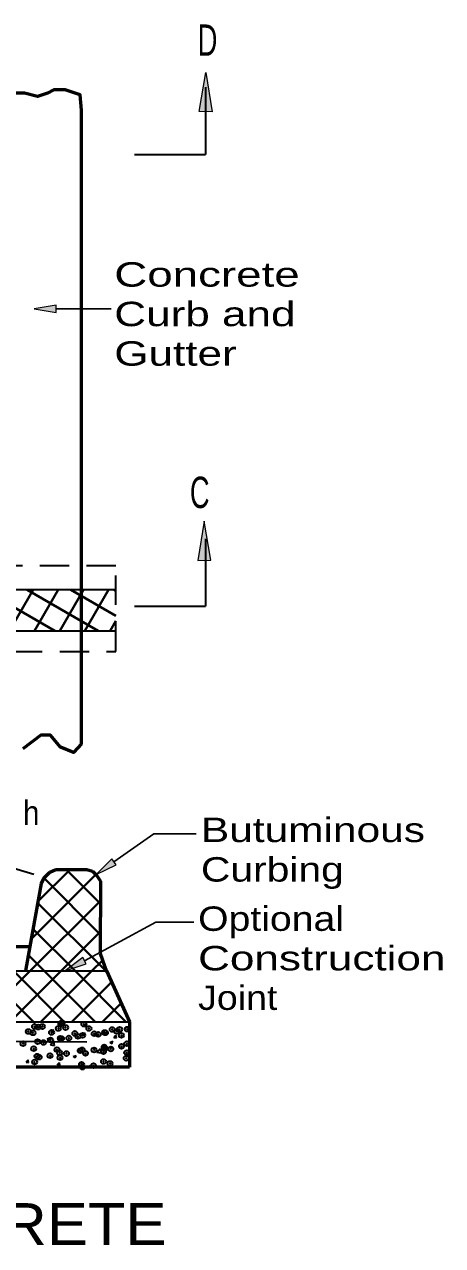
# Model space of a CAD drawing. Extents: x 14 to 49.3, y 28 to 50.
# Drawn here: x 29 to 31.4, y 39.46 to 46.46 of the extents above; entities that cross this region are included whole.
import ezdxf

# ---------------------------------------------------------------- set-up
doc = ezdxf.new("R2010")
doc.units = 0
doc.header["$LTSCALE"] = 0.056
doc.header["$PDMODE"] = 32
doc.header["$PDSIZE"] = 0.028
doc.linetypes.add('MEDIUM_DASHED', pattern=[4.5, 3, -1.5])
for name, color, linetype, lineweight in [('1', 7, 'Continuous', 35), ('2', 7, 'MEDIUM_DASHED', 35), ('3', 7, 'Continuous', 13), ('5', 7, 'Continuous', 35), ('6', 7, 'Continuous', 13)]:
    doc.layers.add(name, color=color, linetype=linetype, lineweight=lineweight)

msp = doc.modelspace()

# ---------------------------------------------------------------- hatches: boundary and pattern name
at = {"layer": '3'}
for points in [[(30.08042, 45.96333), (30.00558, 45.964), (30.04442, 46.188), (30.04442, 46.188)], [(29.18525, 44.81175), (29.18525, 44.85333), (29.06025, 44.83258), (29.06025, 44.83258)], [(29.99833, 43.39033), (30.07317, 43.391), (30.03433, 43.615), (30.03433, 43.615)], [(29.52892, 41.64375), (29.50492, 41.67783), (29.41475, 41.58883), (29.41475, 41.58883)], [(29.35817, 41.07625), (29.3385, 41.113), (29.23817, 41.0355), (29.23817, 41.0355)]]:
    msp.add_hatch(color=256, dxfattribs=at).paths.add_polyline_path(points)

# ---------------------------------------------------------------- linework, layer by layer
at = {"layer": '1'}
for p, q in [((29.52825, 43.22192), (26.00883, 43.22192)), ((26.01817, 42.98625), (29.52825, 42.98625)), ((29.05775, 41.58833), (28.50167, 41.75425)), ((25.95442, 41.0355), (29.01067, 41.0355)), ((29.01067, 41.0355), (29.47383, 41.0355)), ((25.91817, 40.74367), (29.60692, 40.74367)), ((29.15717, 40.68475), (29.16925, 40.69917)), ((29.17217, 40.6835), (29.16925, 40.69917)), ((29.34383, 40.72625), (29.36133, 40.73292)), ((29.34383, 40.72625), (29.35625, 40.71783)), ((29.35633, 40.71783), (29.36133, 40.73292)), ((29.36217, 40.62683), (25.87033, 40.64908)), ((29.13383, 40.64558), (29.15133, 40.65233)), ((29.13383, 40.64558), (29.15133, 40.65233)), ((29.13383, 40.64558), (29.14625, 40.63717)), ((29.14625, 40.63717), (29.15133, 40.65233)), ((29.15292, 40.61108), (29.17242, 40.63133)), ((29.15717, 40.68475), (29.17217, 40.6835)), ((29.17517, 40.60758), (29.17242, 40.63133)), ((29.3365, 40.66908), (29.34858, 40.68342)), ((29.3365, 40.66908), (29.35142, 40.66775)), ((29.3515, 40.66775), (29.34858, 40.68342)), ((29.49308, 40.62558), (29.51058, 40.63225)), ((29.49308, 40.62558), (29.5055, 40.61717)), ((29.5055, 40.61717), (29.51058, 40.63225)), ((29.51583, 40.65342), (29.52792, 40.66775)), ((29.51583, 40.65342), (29.53075, 40.65208)), ((29.53075, 40.65208), (29.52792, 40.66775)), ((29.15292, 40.61108), (29.17517, 40.60758)), ((29.283, 40.54492), (29.3005, 40.55167)), ((29.2955, 40.5365), (29.3005, 40.55167)), ((29.41975, 40.56967), (29.43925, 40.59)), ((29.41975, 40.56967), (29.442, 40.56625)), ((29.442, 40.56625), (29.43925, 40.59)), ((29.01258, 40.51242), (29.02458, 40.52675)), ((29.01258, 40.51242), (29.0275, 40.51108)), ((29.0275, 40.51108), (29.02467, 40.52675)), ((29.19192, 40.49675), (29.20392, 40.51108)), ((29.19192, 40.49675), (29.20683, 40.49542)), ((29.20683, 40.49542), (29.20392, 40.51108)), ((29.20683, 40.49542), (29.20392, 40.51108)), ((29.283, 40.54492), (29.2955, 40.5365)), ((29.37333, 40.48358), (29.38325, 40.49542)), ((29.38542, 40.48358), (29.38325, 40.49542))]:
    msp.add_line(p, q, dxfattribs=at)
at = {"layer": '1', "lineweight": 40}
for p, q in [((28.76908, 43.22192), (29.17733, 42.98625)), ((28.91733, 42.98625), (29.05342, 43.22192)), ((29.01908, 43.22192), (29.42733, 42.98625)), ((29.06167, 42.98625), (29.19775, 43.22192)), ((29.206, 42.98625), (29.34208, 43.22192)), ((29.26908, 43.22192), (29.52825, 43.07225)), ((29.35033, 42.98625), (29.48642, 43.22192)), ((29.51908, 43.22192), (29.52825, 43.21658)), ((29.49467, 42.98625), (29.52825, 43.0445)), ((29.083, 41.43517), (29.26533, 41.6175)), ((29.4395, 41.42025), (29.24242, 41.61725)), ((29.044, 41.21933), (29.41408, 41.58942)), ((29.43808, 41.24483), (29.11592, 41.567)), ((29.03683, 41.0355), (29.43967, 41.43825)), ((29.47067, 41.0355), (29.08117, 41.425)), ((29.29392, 41.0355), (29.05408, 41.27533)), ((29.21367, 41.0355), (29.43825, 41.26008)), ((29.11717, 41.0355), (29.027, 41.12558)), ((29.39042, 41.0355), (29.45125, 41.09625)), ((28.74508, 40.74367), (29.03683, 41.0355)), ((29.05542, 40.74367), (28.76358, 41.0355)), ((28.92183, 40.74367), (29.21367, 41.0355)), ((29.23217, 40.74367), (28.94033, 41.0355)), ((29.09858, 40.74367), (29.39042, 41.0355)), ((29.40892, 40.74367), (29.11717, 41.0355)), ((29.27542, 40.74367), (29.50308, 40.97133)), ((29.58575, 40.74367), (29.29392, 41.0355)), ((29.4765, 41.02967), (29.47067, 41.0355)), ((29.45217, 40.74367), (29.55842, 40.84992))]:
    msp.add_line(p, q, dxfattribs=at)
at = {"layer": '1', "lineweight": 53}
for p, q in [((29.11767, 41.5705), (29.14858, 41.603)), ((29.14858, 41.603), (29.18283, 41.61675)), ((29.18283, 41.61675), (29.36225, 41.61842)), ((29.36225, 41.61842), (29.39483, 41.60817)), ((29.39483, 41.60817), (29.41767, 41.58592)), ((29.03592, 41.17508), (29.10133, 41.53633)), ((29.10133, 41.53633), (29.11767, 41.5705)), ((29.41767, 41.58592), (29.4405, 41.55)), ((29.4405, 41.55), (29.43725, 41.13608)), ((25.93625, 41.17508), (29.03592, 41.17508)), ((29.01067, 41.0355), (29.03592, 41.17508)), ((29.43725, 41.13608), (29.47358, 41.03258)), ((29.47383, 41.0355), (29.60692, 40.74367)), ((29.60692, 40.74367), (29.60692, 40.48358)), ((29.60692, 40.48358), (25.9, 40.48358))]:
    msp.add_line(p, q, dxfattribs=at)
for points in [[(29.33175, 42.338), (29.33175, 45.97183), (29.32233, 46.06017), (29.23808, 46.08967), (29.17258, 46.08967), (29.13517, 46.07), (29.079, 46.05033), (29.00408, 46.07), (28.93858, 46.07), (28.89175, 46.03075)], [(29.33175, 42.338), (29.28492, 42.28892), (29.21, 42.31842), (29.15383, 42.38717), (29.09767, 42.38717), (28.99475, 42.30858)]]:
    msp.add_lwpolyline(points, dxfattribs=at)
at = {"layer": '1'}
for p in [(29.02575, 40.68867), (29.0525, 40.68042), (29.06142, 40.7175), (29.08225, 40.71358), (29.1065, 40.71658), (29.15925, 40.683), (29.19833, 40.7055), (29.21208, 40.73233), (29.21925, 40.73833), (29.24, 40.71092), (29.29267, 40.67733), (29.34408, 40.7305), (29.37342, 40.70533), (29.46367, 40.68275), (29.46867, 40.68117), (29.50683, 40.69967), (29.53125, 40.68942), (29.54983, 40.70067), (29.5935, 40.7015), (28.99558, 40.61892), (29.07917, 40.63042), (29.11242, 40.62558), (29.1535, 40.63967), (29.20908, 40.64917), (29.21608, 40.64792), (29.25817, 40.65058), (29.31075, 40.66042), (29.33742, 40.66675), (29.404, 40.67558), (29.42617, 40.67175), (29.55958, 40.66608), (29.5905, 40.61825), (29.05675, 40.5895), (29.07617, 40.54717), (29.08775, 40.54108), (29.15033, 40.54933), (29.19025, 40.58383), (29.206, 40.56592), (29.20792, 40.53808), (29.245, 40.56183), (29.32367, 40.57825), (29.33433, 40.5835), (29.35367, 40.56308), (29.40292, 40.58258), (29.45717, 40.57258), (29.46067, 40.5995), (29.4655, 40.59083), (29.4995, 40.58817), (29.56017, 40.60325), (29.59058, 40.56692), (29.06208, 40.51308), (29.33133, 40.50033), (29.33717, 40.484), (29.39975, 40.49225), (29.45758, 40.51633), (29.49442, 40.50467), (29.58742, 40.53508)]:
    msp.add_point(p, dxfattribs=at)
at = {"layer": '2'}
for p, q in [((29.52825, 43.35942), (25.99942, 43.35942)), ((29.52825, 42.86833), (29.52825, 43.35942)), ((25.99008, 42.86833), (29.52825, 42.86833))]:
    msp.add_line(p, q, dxfattribs=at)
at = {"layer": '3', "lineweight": 25}
for p, q in [((29.18525, 44.83258), (29.50017, 44.83258)), ((29.51692, 41.66083), (29.74617, 41.82225)), ((29.74617, 41.82225), (29.98808, 41.82225)), ((29.34833, 41.09458), (29.75825, 41.31467)), ((29.75825, 41.31467), (29.976, 41.31467))]:
    msp.add_line(p, q, dxfattribs=at)
at = {"layer": '3'}
for points in [[(30.08042, 45.96333), (30.00558, 45.964), (30.04442, 46.188), (30.04442, 46.188)], [(29.18525, 44.81175), (29.18525, 44.85333), (29.06025, 44.83258), (29.06025, 44.83258)], [(29.99833, 43.39033), (30.07317, 43.391), (30.03433, 43.615), (30.03433, 43.615)], [(29.52892, 41.64375), (29.50492, 41.67783), (29.41475, 41.58883), (29.41475, 41.58883)], [(29.35817, 41.07625), (29.3385, 41.113), (29.23817, 41.0355), (29.23817, 41.0355)]]:
    msp.add_lwpolyline(points, close=True, dxfattribs=at)
at = {"layer": '5'}
for p, q in [((30.04308, 46.10508), (30.04308, 45.71892)), ((29.6345, 45.71892), (30.04308, 45.71892)), ((30.04308, 43.51425), (30.04308, 43.12808)), ((29.6345, 43.12808), (30.04308, 43.12808))]:
    msp.add_line(p, q, dxfattribs=at)
at = {"layer": '6'}
msp.add_line((29.11758, 41.5705), (29.11767, 41.5705), dxfattribs=at)

# ---------------------------------------------------------------- texts
at = {"layer": '1', "width": 0.9}
msp.add_text('h', height=0.14, dxfattribs=at).set_placement((28.99558, 41.87233))
at = {"layer": '3'}
for s, height, width, p in [('Concrete', 0.14, 1.4, (29.51892, 44.96025)), ('Curb and', 0.14, 1.35, (29.51892, 44.73358)), ('Gutter', 0.14, 1.35, (29.51892, 44.50692)), ('Butuminous', 0.14, 1.3, (30.016, 41.77483)), ('Curbing', 0.14, 1.25, (30.016, 41.54817)), ('Optional', 0.14, 1.2, (29.99975, 41.2655)), ('Construction', 0.14, 1.35, (29.99975, 41.03883)), ('Joint', 0.14, 1.15, (29.99975, 40.81217)), ('JOINT THRU CONCRETE', 0.24, 1.1, (25.641, 39.464))]:
    msp.add_text(s, height=height, dxfattribs=dict(at, width=width)).set_placement(p)
at = {"layer": '5', "width": 0.65}
for s, p in [('D', (29.99742, 46.28417)), ('C', (29.95267, 43.69033))]:
    msp.add_text(s, height=0.18, dxfattribs=at).set_placement(p)

doc.saveas('drawing.dxf')
